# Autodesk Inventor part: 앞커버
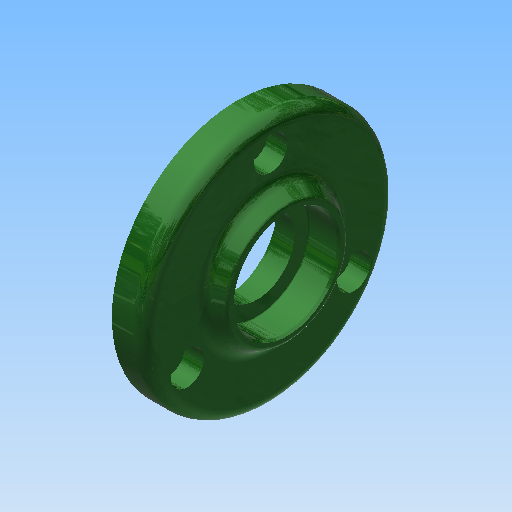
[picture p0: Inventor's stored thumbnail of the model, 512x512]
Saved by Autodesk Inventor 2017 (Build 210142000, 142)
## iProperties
Created: 2015-11
Part Number: 앞커버
Material: 알루미늄 6061
Document SubType Name: Modeling
Designer: mduedu
Density: 1 g/cm^3
Appearance: 매끄러움 - 짙은 산림 녹색
Author: mduedu
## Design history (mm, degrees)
sketch "스케치5"
  geometry: C1 r 30 at (0, 0); 2 further points
  constraints: 2 coincident, 1 centre point
  dimensions: "d66" = 60 diameter of C1
extrude "돌출2" new body sketch "스케치5" distance "d67" = 8; taper "d68" = 0 deg
sketch "스케치9"
  geometry: C1 r 16.5 at (0, 0); 1 further point
  constraints: 1 centre point, 1 coincident
  dimensions: "d146" = 33 diameter of C1
extrude "돌출4" join sketch "스케치9" distance "d147" = 4; taper "d148" = -30 deg
sketch "스케치6"
  geometry: C1 r 16 at (0, 0); 1 further point
  constraints: 1 centre point, 1 coincident
  dimensions: "d69" = 32 diameter of C1
extrude "돌출3" join sketch "스케치6" distance "d70" = 3; taper "d71" = 0 deg
hole "구멍7" diameter "d98" = 25; stored, may be unused: countersink angle "d102" = 90 deg, drill point angle "d104" = 0 deg; dims "d96" = 10, "d97" = 10, "d99" = 6, "d100" = 4, "d101" = 2, "d103" = 3
hole "구멍8" diameter "d107" = 25; stored, may be unused: countersink angle "d111" = 90 deg, drill point angle "d113" = 0 deg; dims "d108" = 6, "d109" = 4, "d110" = 2, "d112" = 7.3, "d151" = 10, "d152" = 10
hole "구멍9" diameter "d116" = 18; stored, may be unused: countersink angle "d120" = 90 deg, drill point angle "d122" = 0 deg; dims "d117" = 6, "d118" = 4, "d119" = 2, "d121" = 7.7, "d154" = 10, "d155" = 10
chamfer "모따기2" distance "d123" = 0.6; stored, may be unused: second distance "d124" = 2, angle "d125" = 30 deg
fillet "모깎기11" dims "d126" = 0.3
fillet "모깎기13" dims "d128" = 3
fillet "모깎기14" dims "d129" = 3
fillet "모깎기15" dims "d130" = 0.3
sketch "스케치8" dims "d131" = 46
  geometry: 3 further points
  constraints: 2 vertical alignment, 1 coincident, 2 other
hole "구멍10" sketch "스케치8" at (0, 23) diameter "d132" = 4.5; stored, may be unused: countersink angle "d136" = 90 deg, drill point angle "d138" = 0 deg; dims "d133" = 6, "d134" = 8, "d135" = 4.6, "d137" = 7.7
chamfer "모따기3" distance "d143" = 1; stored, may be unused: second distance "d144" = 2, angle "d145" = 45 deg
fillet "모깎기16" dims "d149" = 1
node "솔리드2"
pattern_circular "원형 패턴4" dims angle "d140" = 360 deg
